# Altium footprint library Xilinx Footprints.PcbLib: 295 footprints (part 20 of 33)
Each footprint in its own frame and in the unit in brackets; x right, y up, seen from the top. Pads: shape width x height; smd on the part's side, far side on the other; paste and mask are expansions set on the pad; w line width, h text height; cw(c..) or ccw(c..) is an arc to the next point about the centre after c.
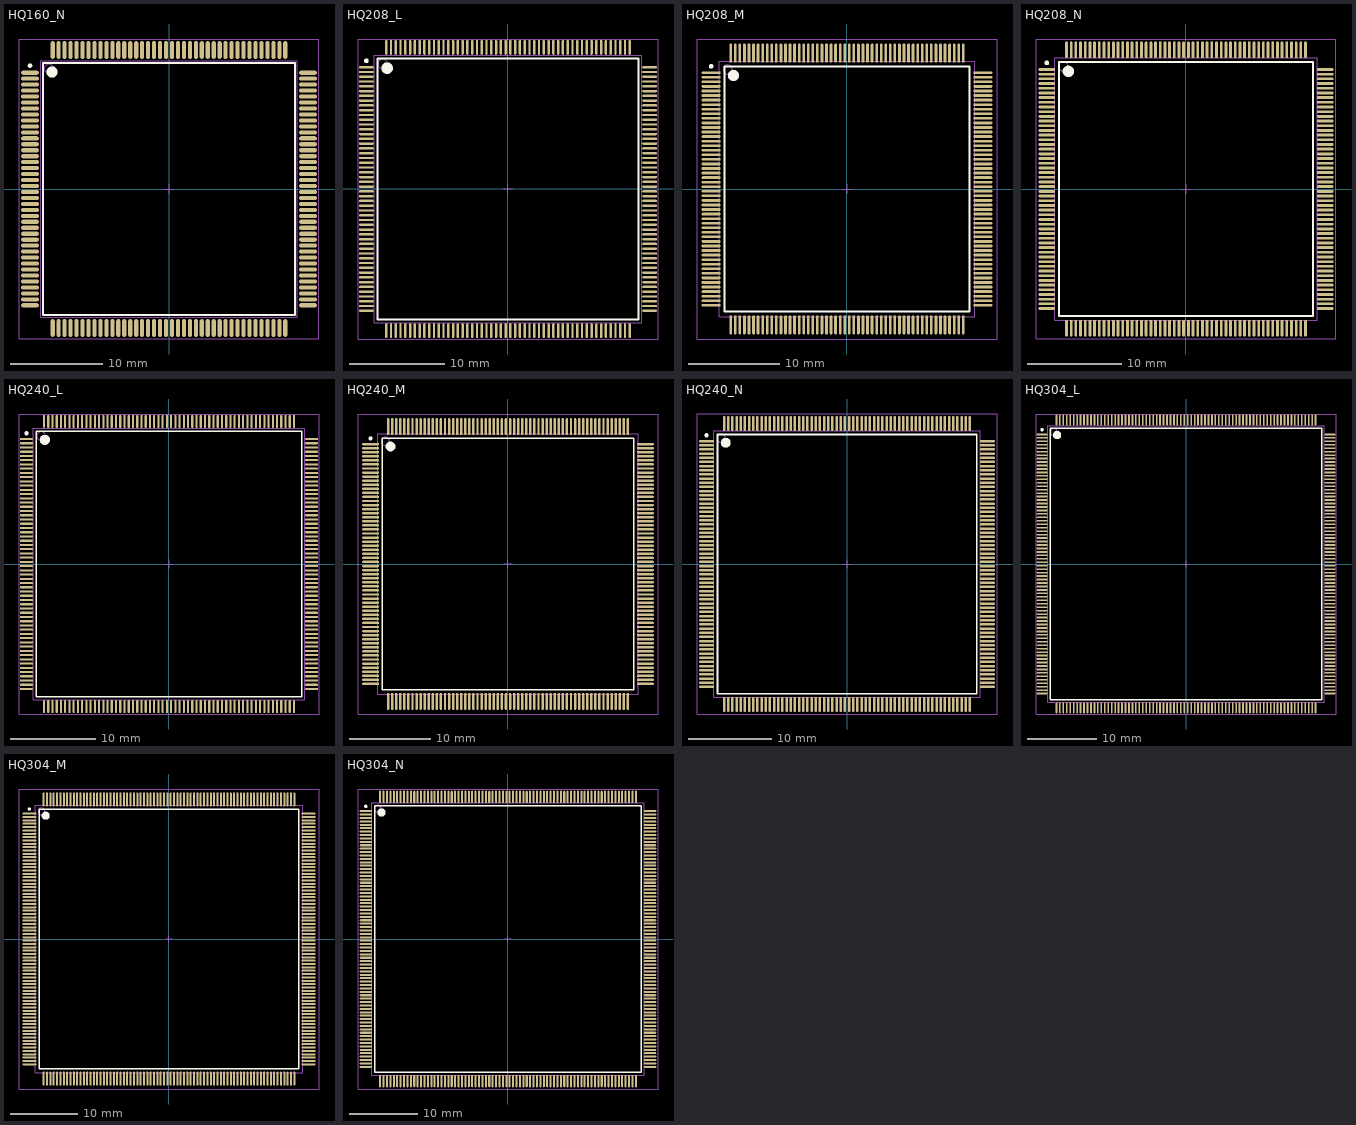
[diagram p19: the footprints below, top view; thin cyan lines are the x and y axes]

## HQ160_N [mm] "160-Pin Heat Sink Quad Flat Pack (HQ160), IPC Medium Density"
height 4.1
pads (160):
  oval 1.95x0.45 smd: 1(-15.15,12.675) 2(-15.15,12.025) 3(-15.15,11.375) 4(-15.15,10.725) 5(-15.15,10.075) 6(-15.15,9.425) 7(-15.15,8.775) 8(-15.15,8.125) 9(-15.15,7.475) 10(-15.15,6.825) 11(-15.15,6.175) 12(-15.15,5.525) 13(-15.15,4.875) 14(-15.15,4.225) 15(-15.15,3.575) 16(-15.15,2.925) 17(-15.15,2.275) 18(-15.15,1.625) 19(-15.15,0.975) 20(-15.15,0.325) 21(-15.15,-0.325) 22(-15.15,-0.975) 23(-15.15,-1.625) 24(-15.15,-2.275) 25(-15.15,-2.925) 26(-15.15,-3.575) 27(-15.15,-4.225) 28(-15.15,-4.875) 29(-15.15,-5.525) 30(-15.15,-6.175) 31(-15.15,-6.825) 32(-15.15,-7.475) 33(-15.15,-8.125) 34(-15.15,-8.775) 35(-15.15,-9.425) 36(-15.15,-10.075) 37(-15.15,-10.725) 38(-15.15,-11.375) 39(-15.15,-12.025) 40(-15.15,-12.675) 81(15.15,-12.675) 82(15.15,-12.025) 83(15.15,-11.375) 84(15.15,-10.725) 85(15.15,-10.075) 86(15.15,-9.425) 87(15.15,-8.775) 88(15.15,-8.125) 89(15.15,-7.475) 90(15.15,-6.825) 91(15.15,-6.175) 92(15.15,-5.525) 93(15.15,-4.875) 94(15.15,-4.225) 95(15.15,-3.575) 96(15.15,-2.925) 97(15.15,-2.275) 98(15.15,-1.625) 99(15.15,-0.975) 100(15.15,-0.325) 101(15.15,0.325) 102(15.15,0.975) 103(15.15,1.625) 104(15.15,2.275) 105(15.15,2.925) 106(15.15,3.575) 107(15.15,4.225) 108(15.15,4.875) 109(15.15,5.525) 110(15.15,6.175) 111(15.15,6.825) 112(15.15,7.475) 113(15.15,8.125) 114(15.15,8.775) 115(15.15,9.425) 116(15.15,10.075) 117(15.15,10.725) 118(15.15,11.375) 119(15.15,12.025) 120(15.15,12.675)
  oval 0.45x1.95 smd: 41(-12.675,-15.15) 42(-12.025,-15.15) 43(-11.375,-15.15) 44(-10.725,-15.15) 45(-10.075,-15.15) 46(-9.425,-15.15) 47(-8.775,-15.15) 48(-8.125,-15.15) 49(-7.475,-15.15) 50(-6.825,-15.15) 51(-6.175,-15.15) 52(-5.525,-15.15) 53(-4.875,-15.15) 54(-4.225,-15.15) 55(-3.575,-15.15) 56(-2.925,-15.15) 57(-2.275,-15.15) 58(-1.625,-15.15) 59(-0.975,-15.15) 60(-0.325,-15.15) 61(0.325,-15.15) 62(0.975,-15.15) 63(1.625,-15.15) 64(2.275,-15.15) 65(2.925,-15.15) 66(3.575,-15.15) 67(4.225,-15.15) 68(4.875,-15.15) 69(5.525,-15.15) 70(6.175,-15.15) 71(6.825,-15.15) 72(7.475,-15.15) 73(8.125,-15.15) 74(8.775,-15.15) 75(9.425,-15.15) 76(10.075,-15.15) 77(10.725,-15.15) 78(11.375,-15.15) 79(12.025,-15.15) 80(12.675,-15.15) 121(12.675,15.15) 122(12.025,15.15) 123(11.375,15.15) 124(10.725,15.15) 125(10.075,15.15) 126(9.425,15.15) 127(8.775,15.15) 128(8.125,15.15) 129(7.475,15.15) 130(6.825,15.15) 131(6.175,15.15) 132(5.525,15.15) 133(4.875,15.15) 134(4.225,15.15) 135(3.575,15.15) 136(2.925,15.15) 137(2.275,15.15) 138(1.625,15.15) 139(0.975,15.15) 140(0.325,15.15) 141(-0.325,15.15) 142(-0.975,15.15) 143(-1.625,15.15) 144(-2.275,15.15) 145(-2.925,15.15) 146(-3.575,15.15) 147(-4.225,15.15) 148(-4.875,15.15) 149(-5.525,15.15) 150(-6.175,15.15) 151(-6.825,15.15) 152(-7.475,15.15) 153(-8.125,15.15) 154(-8.775,15.15) 155(-9.425,15.15) 156(-10.075,15.15) 157(-10.725,15.15) 158(-11.375,15.15) 159(-12.025,15.15) 160(-12.675,15.15)
Top Overlay:
  circle w0.6: c-12.75,12.75 r0.3
  circle w0.25: c-15.15,13.45 r0.125
  lines w0.2: -13.75,-13.75 13.75,-13.75 13.75,13.75 -13.75,13.75 -13.75,-13.75
Mechanical 13:
  circle w0.1: c-13.1,13.1 r0.5
  lines w0.1: -14,-14 14,-14 14,14 -14,14 -14,-14
Mechanical 15:
  lines w0.1: -0.5,0 0.5,0 ; 0,-0.5 0,0.5 ; -16.35,-16.35 16.35,-16.35 16.35,16.35 -16.35,16.35 -16.35,-16.35
3D body: height 4.1, standoff 0, extent -14,-14 14,14

## HQ208_L [mm] "208-Pin Heat Sink Quad Flat Pack (HQ208), IPC High Density"
height 4.1
pads (208):
  oval 1.55x0.25 smd: 1(-14.825,12.75) 2(-14.825,12.25) 3(-14.825,11.75) 4(-14.825,11.25) 5(-14.825,10.75) 6(-14.825,10.25) 7(-14.825,9.75) 8(-14.825,9.25) 9(-14.825,8.75) 10(-14.825,8.25) 11(-14.825,7.75) 12(-14.825,7.25) 13(-14.825,6.75) 14(-14.825,6.25) 15(-14.825,5.75) 16(-14.825,5.25) 17(-14.825,4.75) 18(-14.825,4.25) 19(-14.825,3.75) 20(-14.825,3.25) 21(-14.825,2.75) 22(-14.825,2.25) 23(-14.825,1.75) 24(-14.825,1.25) 25(-14.825,0.75) 26(-14.825,0.25) 27(-14.825,-0.25) 28(-14.825,-0.75) 29(-14.825,-1.25) 30(-14.825,-1.75) 31(-14.825,-2.25) 32(-14.825,-2.75) 33(-14.825,-3.25) 34(-14.825,-3.75) 35(-14.825,-4.25) 36(-14.825,-4.75) 37(-14.825,-5.25) 38(-14.825,-5.75) 39(-14.825,-6.25) 40(-14.825,-6.75) 41(-14.825,-7.25) 42(-14.825,-7.75) 43(-14.825,-8.25) 44(-14.825,-8.75) 45(-14.825,-9.25) 46(-14.825,-9.75) 47(-14.825,-10.25) 48(-14.825,-10.75) 49(-14.825,-11.25) 50(-14.825,-11.75) 51(-14.825,-12.25) 52(-14.825,-12.75) 105(14.825,-12.75) 106(14.825,-12.25) 107(14.825,-11.75) 108(14.825,-11.25) 109(14.825,-10.75) 110(14.825,-10.25) 111(14.825,-9.75) 112(14.825,-9.25) 113(14.825,-8.75) 114(14.825,-8.25) 115(14.825,-7.75) 116(14.825,-7.25) 117(14.825,-6.75) 118(14.825,-6.25) 119(14.825,-5.75) 120(14.825,-5.25) 121(14.825,-4.75) 122(14.825,-4.25) 123(14.825,-3.75) 124(14.825,-3.25) 125(14.825,-2.75) 126(14.825,-2.25) 127(14.825,-1.75) 128(14.825,-1.25) 129(14.825,-0.75) 130(14.825,-0.25) 131(14.825,0.25) 132(14.825,0.75) 133(14.825,1.25) 134(14.825,1.75) 135(14.825,2.25) 136(14.825,2.75) 137(14.825,3.25) 138(14.825,3.75) 139(14.825,4.25) 140(14.825,4.75) 141(14.825,5.25) 142(14.825,5.75) 143(14.825,6.25) 144(14.825,6.75) 145(14.825,7.25) 146(14.825,7.75) 147(14.825,8.25) 148(14.825,8.75) 149(14.825,9.25) 150(14.825,9.75) 151(14.825,10.25) 152(14.825,10.75) 153(14.825,11.25) 154(14.825,11.75) 155(14.825,12.25) 156(14.825,12.75)
  oval 0.25x1.55 smd: 53(-12.75,-14.825) 54(-12.25,-14.825) 55(-11.75,-14.825) 56(-11.25,-14.825) 57(-10.75,-14.825) 58(-10.25,-14.825) 59(-9.75,-14.825) 60(-9.25,-14.825) 61(-8.75,-14.825) 62(-8.25,-14.825) 63(-7.75,-14.825) 64(-7.25,-14.825) 65(-6.75,-14.825) 66(-6.25,-14.825) 67(-5.75,-14.825) 68(-5.25,-14.825) 69(-4.75,-14.825) 70(-4.25,-14.825) 71(-3.75,-14.825) 72(-3.25,-14.825) 73(-2.75,-14.825) 74(-2.25,-14.825) 75(-1.75,-14.825) 76(-1.25,-14.825) 77(-0.75,-14.825) 78(-0.25,-14.825) 79(0.25,-14.825) 80(0.75,-14.825) 81(1.25,-14.825) 82(1.75,-14.825) 83(2.25,-14.825) 84(2.75,-14.825) 85(3.25,-14.825) 86(3.75,-14.825) 87(4.25,-14.825) 88(4.75,-14.825) 89(5.25,-14.825) 90(5.75,-14.825) 91(6.25,-14.825) 92(6.75,-14.825) 93(7.25,-14.825) 94(7.75,-14.825) 95(8.25,-14.825) 96(8.75,-14.825) 97(9.25,-14.825) 98(9.75,-14.825) 99(10.25,-14.825) 100(10.75,-14.825) 101(11.25,-14.825) 102(11.75,-14.825) 103(12.25,-14.825) 104(12.75,-14.825) 157(12.75,14.825) 158(12.25,14.825) 159(11.75,14.825) 160(11.25,14.825) 161(10.75,14.825) 162(10.25,14.825) 163(9.75,14.825) 164(9.25,14.825) 165(8.75,14.825) 166(8.25,14.825) 167(7.75,14.825) 168(7.25,14.825) 169(6.75,14.825) 170(6.25,14.825) 171(5.75,14.825) 172(5.25,14.825) 173(4.75,14.825) 174(4.25,14.825) 175(3.75,14.825) 176(3.25,14.825) 177(2.75,14.825) 178(2.25,14.825) 179(1.75,14.825) 180(1.25,14.825) 181(0.75,14.825) 182(0.25,14.825) 183(-0.25,14.825) 184(-0.75,14.825) 185(-1.25,14.825) 186(-1.75,14.825) 187(-2.25,14.825) 188(-2.75,14.825) 189(-3.25,14.825) 190(-3.75,14.825) 191(-4.25,14.825) 192(-4.75,14.825) 193(-5.25,14.825) 194(-5.75,14.825) 195(-6.25,14.825) 196(-6.75,14.825) 197(-7.25,14.825) 198(-7.75,14.825) 199(-8.25,14.825) 200(-8.75,14.825) 201(-9.25,14.825) 202(-9.75,14.825) 203(-10.25,14.825) 204(-10.75,14.825) 205(-11.25,14.825) 206(-11.75,14.825) 207(-12.25,14.825) 208(-12.75,14.825)
Top Overlay:
  circle w0.6: c-12.65,12.65 r0.3
  circle w0.25: c-14.825,13.425 r0.125
  lines w0.2: -13.65,-13.65 13.65,-13.65 13.65,13.65 -13.65,13.65 -13.65,-13.65
Mechanical 13:
  circle w0.1: c-13.1,13.1 r0.5
  lines w0.1: -14,-14 14,-14 14,14 -14,14 -14,-14
Mechanical 15:
  lines w0.1: -0.5,0 0.5,0 ; 0,-0.5 0,0.5 ; -15.7,-15.7 15.7,-15.7 15.7,15.7 -15.7,15.7 -15.7,-15.7
3D body: height 4.1, standoff 0, extent -14,-14 14,14

## HQ208_M [mm] "208-Pin Heat Sink Quad Flat Pack (HQ208), IPC Low Density"
height 4.1
pads (208):
  oval 2.1x0.3 smd: 1(-14.9,12.75) 2(-14.9,12.25) 3(-14.9,11.75) 4(-14.9,11.25) 5(-14.9,10.75) 6(-14.9,10.25) 7(-14.9,9.75) 8(-14.9,9.25) 9(-14.9,8.75) 10(-14.9,8.25) 11(-14.9,7.75) 12(-14.9,7.25) 13(-14.9,6.75) 14(-14.9,6.25) 15(-14.9,5.75) 16(-14.9,5.25) 17(-14.9,4.75) 18(-14.9,4.25) 19(-14.9,3.75) 20(-14.9,3.25) 21(-14.9,2.75) 22(-14.9,2.25) 23(-14.9,1.75) 24(-14.9,1.25) 25(-14.9,0.75) 26(-14.9,0.25) 27(-14.9,-0.25) 28(-14.9,-0.75) 29(-14.9,-1.25) 30(-14.9,-1.75) 31(-14.9,-2.25) 32(-14.9,-2.75) 33(-14.9,-3.25) 34(-14.9,-3.75) 35(-14.9,-4.25) 36(-14.9,-4.75) 37(-14.9,-5.25) 38(-14.9,-5.75) 39(-14.9,-6.25) 40(-14.9,-6.75) 41(-14.9,-7.25) 42(-14.9,-7.75) 43(-14.9,-8.25) 44(-14.9,-8.75) 45(-14.9,-9.25) 46(-14.9,-9.75) 47(-14.9,-10.25) 48(-14.9,-10.75) 49(-14.9,-11.25) 50(-14.9,-11.75) 51(-14.9,-12.25) 52(-14.9,-12.75) 105(14.9,-12.75) 106(14.9,-12.25) 107(14.9,-11.75) 108(14.9,-11.25) 109(14.9,-10.75) 110(14.9,-10.25) 111(14.9,-9.75) 112(14.9,-9.25) 113(14.9,-8.75) 114(14.9,-8.25) 115(14.9,-7.75) 116(14.9,-7.25) 117(14.9,-6.75) 118(14.9,-6.25) 119(14.9,-5.75) 120(14.9,-5.25) 121(14.9,-4.75) 122(14.9,-4.25) 123(14.9,-3.75) 124(14.9,-3.25) 125(14.9,-2.75) 126(14.9,-2.25) 127(14.9,-1.75) 128(14.9,-1.25) 129(14.9,-0.75) 130(14.9,-0.25) 131(14.9,0.25) 132(14.9,0.75) 133(14.9,1.25) 134(14.9,1.75) 135(14.9,2.25) 136(14.9,2.75) 137(14.9,3.25) 138(14.9,3.75) 139(14.9,4.25) 140(14.9,4.75) 141(14.9,5.25) 142(14.9,5.75) 143(14.9,6.25) 144(14.9,6.75) 145(14.9,7.25) 146(14.9,7.75) 147(14.9,8.25) 148(14.9,8.75) 149(14.9,9.25) 150(14.9,9.75) 151(14.9,10.25) 152(14.9,10.75) 153(14.9,11.25) 154(14.9,11.75) 155(14.9,12.25) 156(14.9,12.75)
  oval 0.3x2.1 smd: 53(-12.75,-14.9) 54(-12.25,-14.9) 55(-11.75,-14.9) 56(-11.25,-14.9) 57(-10.75,-14.9) 58(-10.25,-14.9) 59(-9.75,-14.9) 60(-9.25,-14.9) 61(-8.75,-14.9) 62(-8.25,-14.9) 63(-7.75,-14.9) 64(-7.25,-14.9) 65(-6.75,-14.9) 66(-6.25,-14.9) 67(-5.75,-14.9) 68(-5.25,-14.9) 69(-4.75,-14.9) 70(-4.25,-14.9) 71(-3.75,-14.9) 72(-3.25,-14.9) 73(-2.75,-14.9) 74(-2.25,-14.9) 75(-1.75,-14.9) 76(-1.25,-14.9) 77(-0.75,-14.9) 78(-0.25,-14.9) 79(0.25,-14.9) 80(0.75,-14.9) 81(1.25,-14.9) 82(1.75,-14.9) 83(2.25,-14.9) 84(2.75,-14.9) 85(3.25,-14.9) 86(3.75,-14.9) 87(4.25,-14.9) 88(4.75,-14.9) 89(5.25,-14.9) 90(5.75,-14.9) 91(6.25,-14.9) 92(6.75,-14.9) 93(7.25,-14.9) 94(7.75,-14.9) 95(8.25,-14.9) 96(8.75,-14.9) 97(9.25,-14.9) 98(9.75,-14.9) 99(10.25,-14.9) 100(10.75,-14.9) 101(11.25,-14.9) 102(11.75,-14.9) 103(12.25,-14.9) 104(12.75,-14.9) 157(12.75,14.9) 158(12.25,14.9) 159(11.75,14.9) 160(11.25,14.9) 161(10.75,14.9) 162(10.25,14.9) 163(9.75,14.9) 164(9.25,14.9) 165(8.75,14.9) 166(8.25,14.9) 167(7.75,14.9) 168(7.25,14.9) 169(6.75,14.9) 170(6.25,14.9) 171(5.75,14.9) 172(5.25,14.9) 173(4.75,14.9) 174(4.25,14.9) 175(3.75,14.9) 176(3.25,14.9) 177(2.75,14.9) 178(2.25,14.9) 179(1.75,14.9) 180(1.25,14.9) 181(0.75,14.9) 182(0.25,14.9) 183(-0.25,14.9) 184(-0.75,14.9) 185(-1.25,14.9) 186(-1.75,14.9) 187(-2.25,14.9) 188(-2.75,14.9) 189(-3.25,14.9) 190(-3.75,14.9) 191(-4.25,14.9) 192(-4.75,14.9) 193(-5.25,14.9) 194(-5.75,14.9) 195(-6.25,14.9) 196(-6.75,14.9) 197(-7.25,14.9) 198(-7.75,14.9) 199(-8.25,14.9) 200(-8.75,14.9) 201(-9.25,14.9) 202(-9.75,14.9) 203(-10.25,14.9) 204(-10.75,14.9) 205(-11.25,14.9) 206(-11.75,14.9) 207(-12.25,14.9) 208(-12.75,14.9)
Top Overlay:
  circle w0.6: c-12.45,12.45 r0.3
  circle w0.25: c-14.9,13.45 r0.125
  lines w0.2: -13.45,-13.45 13.45,-13.45 13.45,13.45 -13.45,13.45 -13.45,-13.45
Mechanical 13:
  circle w0.1: c-13.1,13.1 r0.5
  lines w0.1: -14,-14 14,-14 14,14 -14,14 -14,-14
Mechanical 15:
  lines w0.1: -0.5,0 0.5,0 ; 0,-0.5 0,0.5 ; -16.45,-16.45 16.45,-16.45 16.45,16.45 -16.45,16.45 -16.45,-16.45
3D body: height 4.1, standoff 0, extent -14,-14 14,14

## HQ208_N [mm] "208-Pin Heat Sink Quad Flat Pack (HQ208), IPC Medium Density"
height 4.1
pads (208):
  oval 1.8x0.3 smd: 1(-14.85,12.75) 2(-14.85,12.25) 3(-14.85,11.75) 4(-14.85,11.25) 5(-14.85,10.75) 6(-14.85,10.25) 7(-14.85,9.75) 8(-14.85,9.25) 9(-14.85,8.75) 10(-14.85,8.25) 11(-14.85,7.75) 12(-14.85,7.25) 13(-14.85,6.75) 14(-14.85,6.25) 15(-14.85,5.75) 16(-14.85,5.25) 17(-14.85,4.75) 18(-14.85,4.25) 19(-14.85,3.75) 20(-14.85,3.25) 21(-14.85,2.75) 22(-14.85,2.25) 23(-14.85,1.75) 24(-14.85,1.25) 25(-14.85,0.75) 26(-14.85,0.25) 27(-14.85,-0.25) 28(-14.85,-0.75) 29(-14.85,-1.25) 30(-14.85,-1.75) 31(-14.85,-2.25) 32(-14.85,-2.75) 33(-14.85,-3.25) 34(-14.85,-3.75) 35(-14.85,-4.25) 36(-14.85,-4.75) 37(-14.85,-5.25) 38(-14.85,-5.75) 39(-14.85,-6.25) 40(-14.85,-6.75) 41(-14.85,-7.25) 42(-14.85,-7.75) 43(-14.85,-8.25) 44(-14.85,-8.75) 45(-14.85,-9.25) 46(-14.85,-9.75) 47(-14.85,-10.25) 48(-14.85,-10.75) 49(-14.85,-11.25) 50(-14.85,-11.75) 51(-14.85,-12.25) 52(-14.85,-12.75) 105(14.85,-12.75) 106(14.85,-12.25) 107(14.85,-11.75) 108(14.85,-11.25) 109(14.85,-10.75) 110(14.85,-10.25) 111(14.85,-9.75) 112(14.85,-9.25) 113(14.85,-8.75) 114(14.85,-8.25) 115(14.85,-7.75) 116(14.85,-7.25) 117(14.85,-6.75) 118(14.85,-6.25) 119(14.85,-5.75) 120(14.85,-5.25) 121(14.85,-4.75) 122(14.85,-4.25) 123(14.85,-3.75) 124(14.85,-3.25) 125(14.85,-2.75) 126(14.85,-2.25) 127(14.85,-1.75) 128(14.85,-1.25) 129(14.85,-0.75) 130(14.85,-0.25) 131(14.85,0.25) 132(14.85,0.75) 133(14.85,1.25) 134(14.85,1.75) 135(14.85,2.25) 136(14.85,2.75) 137(14.85,3.25) 138(14.85,3.75) 139(14.85,4.25) 140(14.85,4.75) 141(14.85,5.25) 142(14.85,5.75) 143(14.85,6.25) 144(14.85,6.75) 145(14.85,7.25) 146(14.85,7.75) 147(14.85,8.25) 148(14.85,8.75) 149(14.85,9.25) 150(14.85,9.75) 151(14.85,10.25) 152(14.85,10.75) 153(14.85,11.25) 154(14.85,11.75) 155(14.85,12.25) 156(14.85,12.75)
  oval 0.3x1.8 smd: 53(-12.75,-14.85) 54(-12.25,-14.85) 55(-11.75,-14.85) 56(-11.25,-14.85) 57(-10.75,-14.85) 58(-10.25,-14.85) 59(-9.75,-14.85) 60(-9.25,-14.85) 61(-8.75,-14.85) 62(-8.25,-14.85) 63(-7.75,-14.85) 64(-7.25,-14.85) 65(-6.75,-14.85) 66(-6.25,-14.85) 67(-5.75,-14.85) 68(-5.25,-14.85) 69(-4.75,-14.85) 70(-4.25,-14.85) 71(-3.75,-14.85) 72(-3.25,-14.85) 73(-2.75,-14.85) 74(-2.25,-14.85) 75(-1.75,-14.85) 76(-1.25,-14.85) 77(-0.75,-14.85) 78(-0.25,-14.85) 79(0.25,-14.85) 80(0.75,-14.85) 81(1.25,-14.85) 82(1.75,-14.85) 83(2.25,-14.85) 84(2.75,-14.85) 85(3.25,-14.85) 86(3.75,-14.85) 87(4.25,-14.85) 88(4.75,-14.85) 89(5.25,-14.85) 90(5.75,-14.85) 91(6.25,-14.85) 92(6.75,-14.85) 93(7.25,-14.85) 94(7.75,-14.85) 95(8.25,-14.85) 96(8.75,-14.85) 97(9.25,-14.85) 98(9.75,-14.85) 99(10.25,-14.85) 100(10.75,-14.85) 101(11.25,-14.85) 102(11.75,-14.85) 103(12.25,-14.85) 104(12.75,-14.85) 157(12.75,14.85) 158(12.25,14.85) 159(11.75,14.85) 160(11.25,14.85) 161(10.75,14.85) 162(10.25,14.85) 163(9.75,14.85) 164(9.25,14.85) 165(8.75,14.85) 166(8.25,14.85) 167(7.75,14.85) 168(7.25,14.85) 169(6.75,14.85) 170(6.25,14.85) 171(5.75,14.85) 172(5.25,14.85) 173(4.75,14.85) 174(4.25,14.85) 175(3.75,14.85) 176(3.25,14.85) 177(2.75,14.85) 178(2.25,14.85) 179(1.75,14.85) 180(1.25,14.85) 181(0.75,14.85) 182(0.25,14.85) 183(-0.25,14.85) 184(-0.75,14.85) 185(-1.25,14.85) 186(-1.75,14.85) 187(-2.25,14.85) 188(-2.75,14.85) 189(-3.25,14.85) 190(-3.75,14.85) 191(-4.25,14.85) 192(-4.75,14.85) 193(-5.25,14.85) 194(-5.75,14.85) 195(-6.25,14.85) 196(-6.75,14.85) 197(-7.25,14.85) 198(-7.75,14.85) 199(-8.25,14.85) 200(-8.75,14.85) 201(-9.25,14.85) 202(-9.75,14.85) 203(-10.25,14.85) 204(-10.75,14.85) 205(-11.25,14.85) 206(-11.75,14.85) 207(-12.25,14.85) 208(-12.75,14.85)
Top Overlay:
  circle w0.6: c-12.55,12.55 r0.3
  circle w0.25: c-14.85,13.45 r0.125
  lines w0.2: -13.55,-13.55 13.55,-13.55 13.55,13.55 -13.55,13.55 -13.55,-13.55
Mechanical 13:
  circle w0.1: c-13.1,13.1 r0.5
  lines w0.1: -14,-14 14,-14 14,14 -14,14 -14,-14
Mechanical 15:
  lines w0.1: -0.5,0 0.5,0 ; 0,-0.5 0,0.5 ; -16,-16 16,-16 16,16 -16,16 -16,-16
3D body: height 4.1, standoff 0, extent -14,-14 14,14

## HQ240_L [mm] "240-Pin Heat Sink Quad Flat Pack (HQ240), IPC High Density"
height 4.1
pads (240):
  oval 1.55x0.25 smd: 1(-16.825,14.75) 2(-16.825,14.25) 3(-16.825,13.75) 4(-16.825,13.25) 5(-16.825,12.75) 6(-16.825,12.25) 7(-16.825,11.75) 8(-16.825,11.25) 9(-16.825,10.75) 10(-16.825,10.25) 11(-16.825,9.75) 12(-16.825,9.25) 13(-16.825,8.75) 14(-16.825,8.25) 15(-16.825,7.75) 16(-16.825,7.25) 17(-16.825,6.75) 18(-16.825,6.25) 19(-16.825,5.75) 20(-16.825,5.25) 21(-16.825,4.75) 22(-16.825,4.25) 23(-16.825,3.75) 24(-16.825,3.25) 25(-16.825,2.75) 26(-16.825,2.25) 27(-16.825,1.75) 28(-16.825,1.25) 29(-16.825,0.75) 30(-16.825,0.25) 31(-16.825,-0.25) 32(-16.825,-0.75) 33(-16.825,-1.25) 34(-16.825,-1.75) 35(-16.825,-2.25) 36(-16.825,-2.75) 37(-16.825,-3.25) 38(-16.825,-3.75) 39(-16.825,-4.25) 40(-16.825,-4.75) 41(-16.825,-5.25) 42(-16.825,-5.75) 43(-16.825,-6.25) 44(-16.825,-6.75) 45(-16.825,-7.25) 46(-16.825,-7.75) 47(-16.825,-8.25) 48(-16.825,-8.75) 49(-16.825,-9.25) 50(-16.825,-9.75) 51(-16.825,-10.25) 52(-16.825,-10.75) 53(-16.825,-11.25) 54(-16.825,-11.75) 55(-16.825,-12.25) 56(-16.825,-12.75) 57(-16.825,-13.25) 58(-16.825,-13.75) 59(-16.825,-14.25) 60(-16.825,-14.75) 121(16.825,-14.75) 122(16.825,-14.25) 123(16.825,-13.75) 124(16.825,-13.25) 125(16.825,-12.75) 126(16.825,-12.25) 127(16.825,-11.75) 128(16.825,-11.25) 129(16.825,-10.75) 130(16.825,-10.25) 131(16.825,-9.75) 132(16.825,-9.25) 133(16.825,-8.75) 134(16.825,-8.25) 135(16.825,-7.75) 136(16.825,-7.25) 137(16.825,-6.75) 138(16.825,-6.25) 139(16.825,-5.75) 140(16.825,-5.25) 141(16.825,-4.75) 142(16.825,-4.25) 143(16.825,-3.75) 144(16.825,-3.25) 145(16.825,-2.75) 146(16.825,-2.25) 147(16.825,-1.75) 148(16.825,-1.25) 149(16.825,-0.75) 150(16.825,-0.25) 151(16.825,0.25) 152(16.825,0.75) 153(16.825,1.25) 154(16.825,1.75) 155(16.825,2.25) 156(16.825,2.75) 157(16.825,3.25) 158(16.825,3.75) 159(16.825,4.25) 160(16.825,4.75) 161(16.825,5.25) 162(16.825,5.75) 163(16.825,6.25) 164(16.825,6.75) 165(16.825,7.25) 166(16.825,7.75) 167(16.825,8.25) 168(16.825,8.75) 169(16.825,9.25) 170(16.825,9.75) 171(16.825,10.25) 172(16.825,10.75) 173(16.825,11.25) 174(16.825,11.75) 175(16.825,12.25) 176(16.825,12.75) 177(16.825,13.25) 178(16.825,13.75) 179(16.825,14.25) 180(16.825,14.75)
  oval 0.25x1.55 smd: 61(-14.75,-16.825) 62(-14.25,-16.825) 63(-13.75,-16.825) 64(-13.25,-16.825) 65(-12.75,-16.825) 66(-12.25,-16.825) 67(-11.75,-16.825) 68(-11.25,-16.825) 69(-10.75,-16.825) 70(-10.25,-16.825) 71(-9.75,-16.825) 72(-9.25,-16.825) 73(-8.75,-16.825) 74(-8.25,-16.825) 75(-7.75,-16.825) 76(-7.25,-16.825) 77(-6.75,-16.825) 78(-6.25,-16.825) 79(-5.75,-16.825) 80(-5.25,-16.825) 81(-4.75,-16.825) 82(-4.25,-16.825) 83(-3.75,-16.825) 84(-3.25,-16.825) 85(-2.75,-16.825) 86(-2.25,-16.825) 87(-1.75,-16.825) 88(-1.25,-16.825) 89(-0.75,-16.825) 90(-0.25,-16.825) 91(0.25,-16.825) 92(0.75,-16.825) 93(1.25,-16.825) 94(1.75,-16.825) 95(2.25,-16.825) 96(2.75,-16.825) 97(3.25,-16.825) 98(3.75,-16.825) 99(4.25,-16.825) 100(4.75,-16.825) 101(5.25,-16.825) 102(5.75,-16.825) 103(6.25,-16.825) 104(6.75,-16.825) 105(7.25,-16.825) 106(7.75,-16.825) 107(8.25,-16.825) 108(8.75,-16.825) 109(9.25,-16.825) 110(9.75,-16.825) 111(10.25,-16.825) 112(10.75,-16.825) 113(11.25,-16.825) 114(11.75,-16.825) 115(12.25,-16.825) 116(12.75,-16.825) 117(13.25,-16.825) 118(13.75,-16.825) 119(14.25,-16.825) 120(14.75,-16.825) 181(14.75,16.825) 182(14.25,16.825) 183(13.75,16.825) 184(13.25,16.825) 185(12.75,16.825) 186(12.25,16.825) 187(11.75,16.825) 188(11.25,16.825) 189(10.75,16.825) 190(10.25,16.825) 191(9.75,16.825) 192(9.25,16.825) 193(8.75,16.825) 194(8.25,16.825) 195(7.75,16.825) 196(7.25,16.825) 197(6.75,16.825) 198(6.25,16.825) 199(5.75,16.825) 200(5.25,16.825) 201(4.75,16.825) 202(4.25,16.825) 203(3.75,16.825) 204(3.25,16.825) 205(2.75,16.825) 206(2.25,16.825) 207(1.75,16.825) 208(1.25,16.825) 209(0.75,16.825) 210(0.25,16.825) 211(-0.25,16.825) 212(-0.75,16.825) 213(-1.25,16.825) 214(-1.75,16.825) 215(-2.25,16.825) 216(-2.75,16.825) 217(-3.25,16.825) 218(-3.75,16.825) 219(-4.25,16.825) 220(-4.75,16.825) 221(-5.25,16.825) 222(-5.75,16.825) 223(-6.25,16.825) 224(-6.75,16.825) 225(-7.25,16.825) 226(-7.75,16.825) 227(-8.25,16.825) 228(-8.75,16.825) 229(-9.25,16.825) 230(-9.75,16.825) 231(-10.25,16.825) 232(-10.75,16.825) 233(-11.25,16.825) 234(-11.75,16.825) 235(-12.25,16.825) 236(-12.75,16.825) 237(-13.25,16.825) 238(-13.75,16.825) 239(-14.25,16.825) 240(-14.75,16.825)
Top Overlay:
  circle w0.6: c-14.65,14.65 r0.3
  circle w0.25: c-16.825,15.425 r0.125
  lines w0.2: -15.65,-15.65 15.65,-15.65 15.65,15.65 -15.65,15.65 -15.65,-15.65
Mechanical 13:
  circle w0.1: c-15.1,15.1 r0.5
  lines w0.1: -16,-16 16,-16 16,16 -16,16 -16,-16
Mechanical 15:
  lines w0.1: -0.5,0 0.5,0 ; 0,-0.5 0,0.5 ; -17.7,-17.7 17.7,-17.7 17.7,17.7 -17.7,17.7 -17.7,-17.7
3D body: height 4.1, standoff 0, extent -16,-16 16,16

## HQ240_M [mm] "240-Pin Heat Sink Quad Flat Pack (HQ240), IPC Low Density"
height 4.1
pads (240):
  oval 2.1x0.3 smd: 1(-16.9,14.75) 2(-16.9,14.25) 3(-16.9,13.75) 4(-16.9,13.25) 5(-16.9,12.75) 6(-16.9,12.25) 7(-16.9,11.75) 8(-16.9,11.25) 9(-16.9,10.75) 10(-16.9,10.25) 11(-16.9,9.75) 12(-16.9,9.25) 13(-16.9,8.75) 14(-16.9,8.25) 15(-16.9,7.75) 16(-16.9,7.25) 17(-16.9,6.75) 18(-16.9,6.25) 19(-16.9,5.75) 20(-16.9,5.25) 21(-16.9,4.75) 22(-16.9,4.25) 23(-16.9,3.75) 24(-16.9,3.25) 25(-16.9,2.75) 26(-16.9,2.25) 27(-16.9,1.75) 28(-16.9,1.25) 29(-16.9,0.75) 30(-16.9,0.25) 31(-16.9,-0.25) 32(-16.9,-0.75) 33(-16.9,-1.25) 34(-16.9,-1.75) 35(-16.9,-2.25) 36(-16.9,-2.75) 37(-16.9,-3.25) 38(-16.9,-3.75) 39(-16.9,-4.25) 40(-16.9,-4.75) 41(-16.9,-5.25) 42(-16.9,-5.75) 43(-16.9,-6.25) 44(-16.9,-6.75) 45(-16.9,-7.25) 46(-16.9,-7.75) 47(-16.9,-8.25) 48(-16.9,-8.75) 49(-16.9,-9.25) 50(-16.9,-9.75) 51(-16.9,-10.25) 52(-16.9,-10.75) 53(-16.9,-11.25) 54(-16.9,-11.75) 55(-16.9,-12.25) 56(-16.9,-12.75) 57(-16.9,-13.25) 58(-16.9,-13.75) 59(-16.9,-14.25) 60(-16.9,-14.75) 121(16.9,-14.75) 122(16.9,-14.25) 123(16.9,-13.75) 124(16.9,-13.25) 125(16.9,-12.75) 126(16.9,-12.25) 127(16.9,-11.75) 128(16.9,-11.25) 129(16.9,-10.75) 130(16.9,-10.25) 131(16.9,-9.75) 132(16.9,-9.25) 133(16.9,-8.75) 134(16.9,-8.25) 135(16.9,-7.75) 136(16.9,-7.25) 137(16.9,-6.75) 138(16.9,-6.25) 139(16.9,-5.75) 140(16.9,-5.25) 141(16.9,-4.75) 142(16.9,-4.25) 143(16.9,-3.75) 144(16.9,-3.25) 145(16.9,-2.75) 146(16.9,-2.25) 147(16.9,-1.75) 148(16.9,-1.25) 149(16.9,-0.75) 150(16.9,-0.25) 151(16.9,0.25) 152(16.9,0.75) 153(16.9,1.25) 154(16.9,1.75) 155(16.9,2.25) 156(16.9,2.75) 157(16.9,3.25) 158(16.9,3.75) 159(16.9,4.25) 160(16.9,4.75) 161(16.9,5.25) 162(16.9,5.75) 163(16.9,6.25) 164(16.9,6.75) 165(16.9,7.25) 166(16.9,7.75) 167(16.9,8.25) 168(16.9,8.75) 169(16.9,9.25) 170(16.9,9.75) 171(16.9,10.25) 172(16.9,10.75) 173(16.9,11.25) 174(16.9,11.75) 175(16.9,12.25) 176(16.9,12.75) 177(16.9,13.25) 178(16.9,13.75) 179(16.9,14.25) 180(16.9,14.75)
  oval 0.3x2.1 smd: 61(-14.75,-16.9) 62(-14.25,-16.9) 63(-13.75,-16.9) 64(-13.25,-16.9) 65(-12.75,-16.9) 66(-12.25,-16.9) 67(-11.75,-16.9) 68(-11.25,-16.9) 69(-10.75,-16.9) 70(-10.25,-16.9) 71(-9.75,-16.9) 72(-9.25,-16.9) 73(-8.75,-16.9) 74(-8.25,-16.9) 75(-7.75,-16.9) 76(-7.25,-16.9) 77(-6.75,-16.9) 78(-6.25,-16.9) 79(-5.75,-16.9) 80(-5.25,-16.9) 81(-4.75,-16.9) 82(-4.25,-16.9) 83(-3.75,-16.9) 84(-3.25,-16.9) 85(-2.75,-16.9) 86(-2.25,-16.9) 87(-1.75,-16.9) 88(-1.25,-16.9) 89(-0.75,-16.9) 90(-0.25,-16.9) 91(0.25,-16.9) 92(0.75,-16.9) 93(1.25,-16.9) 94(1.75,-16.9) 95(2.25,-16.9) 96(2.75,-16.9) 97(3.25,-16.9) 98(3.75,-16.9) 99(4.25,-16.9) 100(4.75,-16.9) 101(5.25,-16.9) 102(5.75,-16.9) 103(6.25,-16.9) 104(6.75,-16.9) 105(7.25,-16.9) 106(7.75,-16.9) 107(8.25,-16.9) 108(8.75,-16.9) 109(9.25,-16.9) 110(9.75,-16.9) 111(10.25,-16.9) 112(10.75,-16.9) 113(11.25,-16.9) 114(11.75,-16.9) 115(12.25,-16.9) 116(12.75,-16.9) 117(13.25,-16.9) 118(13.75,-16.9) 119(14.25,-16.9) 120(14.75,-16.9) 181(14.75,16.9) 182(14.25,16.9) 183(13.75,16.9) 184(13.25,16.9) 185(12.75,16.9) 186(12.25,16.9) 187(11.75,16.9) 188(11.25,16.9) 189(10.75,16.9) 190(10.25,16.9) 191(9.75,16.9) 192(9.25,16.9) 193(8.75,16.9) 194(8.25,16.9) 195(7.75,16.9) 196(7.25,16.9) 197(6.75,16.9) 198(6.25,16.9) 199(5.75,16.9) 200(5.25,16.9) 201(4.75,16.9) 202(4.25,16.9) 203(3.75,16.9) 204(3.25,16.9) 205(2.75,16.9) 206(2.25,16.9) 207(1.75,16.9) 208(1.25,16.9) 209(0.75,16.9) 210(0.25,16.9) 211(-0.25,16.9) 212(-0.75,16.9) 213(-1.25,16.9) 214(-1.75,16.9) 215(-2.25,16.9) 216(-2.75,16.9) 217(-3.25,16.9) 218(-3.75,16.9) 219(-4.25,16.9) 220(-4.75,16.9) 221(-5.25,16.9) 222(-5.75,16.9) 223(-6.25,16.9) 224(-6.75,16.9) 225(-7.25,16.9) 226(-7.75,16.9) 227(-8.25,16.9) 228(-8.75,16.9) 229(-9.25,16.9) 230(-9.75,16.9) 231(-10.25,16.9) 232(-10.75,16.9) 233(-11.25,16.9) 234(-11.75,16.9) 235(-12.25,16.9) 236(-12.75,16.9) 237(-13.25,16.9) 238(-13.75,16.9) 239(-14.25,16.9) 240(-14.75,16.9)
Top Overlay:
  circle w0.6: c-14.45,14.45 r0.3
  circle w0.25: c-16.9,15.45 r0.125
  lines w0.2: -15.45,-15.45 15.45,-15.45 15.45,15.45 -15.45,15.45 -15.45,-15.45
Mechanical 13:
  circle w0.1: c-15.1,15.1 r0.5
  lines w0.1: -16,-16 16,-16 16,16 -16,16 -16,-16
Mechanical 15:
  lines w0.1: -0.5,0 0.5,0 ; 0,-0.5 0,0.5 ; -18.45,-18.45 18.45,-18.45 18.45,18.45 -18.45,18.45 -18.45,-18.45
3D body: height 4.1, standoff 0, extent -16,-16 16,16

## HQ240_N [mm] "240-Pin Heat Sink Quad Flat Pack (HQ240), IPC Medium Density"
height 4.1
pads (240):
  oval 1.8x0.3 smd: 1(-16.85,14.75) 2(-16.85,14.25) 3(-16.85,13.75) 4(-16.85,13.25) 5(-16.85,12.75) 6(-16.85,12.25) 7(-16.85,11.75) 8(-16.85,11.25) 9(-16.85,10.75) 10(-16.85,10.25) 11(-16.85,9.75) 12(-16.85,9.25) 13(-16.85,8.75) 14(-16.85,8.25) 15(-16.85,7.75) 16(-16.85,7.25) 17(-16.85,6.75) 18(-16.85,6.25) 19(-16.85,5.75) 20(-16.85,5.25) 21(-16.85,4.75) 22(-16.85,4.25) 23(-16.85,3.75) 24(-16.85,3.25) 25(-16.85,2.75) 26(-16.85,2.25) 27(-16.85,1.75) 28(-16.85,1.25) 29(-16.85,0.75) 30(-16.85,0.25) 31(-16.85,-0.25) 32(-16.85,-0.75) 33(-16.85,-1.25) 34(-16.85,-1.75) 35(-16.85,-2.25) 36(-16.85,-2.75) 37(-16.85,-3.25) 38(-16.85,-3.75) 39(-16.85,-4.25) 40(-16.85,-4.75) 41(-16.85,-5.25) 42(-16.85,-5.75) 43(-16.85,-6.25) 44(-16.85,-6.75) 45(-16.85,-7.25) 46(-16.85,-7.75) 47(-16.85,-8.25) 48(-16.85,-8.75) 49(-16.85,-9.25) 50(-16.85,-9.75) 51(-16.85,-10.25) 52(-16.85,-10.75) 53(-16.85,-11.25) 54(-16.85,-11.75) 55(-16.85,-12.25) 56(-16.85,-12.75) 57(-16.85,-13.25) 58(-16.85,-13.75) 59(-16.85,-14.25) 60(-16.85,-14.75) 121(16.85,-14.75) 122(16.85,-14.25) 123(16.85,-13.75) 124(16.85,-13.25) 125(16.85,-12.75) 126(16.85,-12.25) 127(16.85,-11.75) 128(16.85,-11.25) 129(16.85,-10.75) 130(16.85,-10.25) 131(16.85,-9.75) 132(16.85,-9.25) 133(16.85,-8.75) 134(16.85,-8.25) 135(16.85,-7.75) 136(16.85,-7.25) 137(16.85,-6.75) 138(16.85,-6.25) 139(16.85,-5.75) 140(16.85,-5.25) 141(16.85,-4.75) 142(16.85,-4.25) 143(16.85,-3.75) 144(16.85,-3.25) 145(16.85,-2.75) 146(16.85,-2.25) 147(16.85,-1.75) 148(16.85,-1.25) 149(16.85,-0.75) 150(16.85,-0.25) 151(16.85,0.25) 152(16.85,0.75) 153(16.85,1.25) 154(16.85,1.75) 155(16.85,2.25) 156(16.85,2.75) 157(16.85,3.25) 158(16.85,3.75) 159(16.85,4.25) 160(16.85,4.75) 161(16.85,5.25) 162(16.85,5.75) 163(16.85,6.25) 164(16.85,6.75) 165(16.85,7.25) 166(16.85,7.75) 167(16.85,8.25) 168(16.85,8.75) 169(16.85,9.25) 170(16.85,9.75) 171(16.85,10.25) 172(16.85,10.75) 173(16.85,11.25) 174(16.85,11.75) 175(16.85,12.25) 176(16.85,12.75) 177(16.85,13.25) 178(16.85,13.75) 179(16.85,14.25) 180(16.85,14.75)
  oval 0.3x1.8 smd: 61(-14.75,-16.85) 62(-14.25,-16.85) 63(-13.75,-16.85) 64(-13.25,-16.85) 65(-12.75,-16.85) 66(-12.25,-16.85) 67(-11.75,-16.85) 68(-11.25,-16.85) 69(-10.75,-16.85) 70(-10.25,-16.85) 71(-9.75,-16.85) 72(-9.25,-16.85) 73(-8.75,-16.85) 74(-8.25,-16.85) 75(-7.75,-16.85) 76(-7.25,-16.85) 77(-6.75,-16.85) 78(-6.25,-16.85) 79(-5.75,-16.85) 80(-5.25,-16.85) 81(-4.75,-16.85) 82(-4.25,-16.85) 83(-3.75,-16.85) 84(-3.25,-16.85) 85(-2.75,-16.85) 86(-2.25,-16.85) 87(-1.75,-16.85) 88(-1.25,-16.85) 89(-0.75,-16.85) 90(-0.25,-16.85) 91(0.25,-16.85) 92(0.75,-16.85) 93(1.25,-16.85) 94(1.75,-16.85) 95(2.25,-16.85) 96(2.75,-16.85) 97(3.25,-16.85) 98(3.75,-16.85) 99(4.25,-16.85) 100(4.75,-16.85) 101(5.25,-16.85) 102(5.75,-16.85) 103(6.25,-16.85) 104(6.75,-16.85) 105(7.25,-16.85) 106(7.75,-16.85) 107(8.25,-16.85) 108(8.75,-16.85) 109(9.25,-16.85) 110(9.75,-16.85) 111(10.25,-16.85) 112(10.75,-16.85) 113(11.25,-16.85) 114(11.75,-16.85) 115(12.25,-16.85) 116(12.75,-16.85) 117(13.25,-16.85) 118(13.75,-16.85) 119(14.25,-16.85) 120(14.75,-16.85) 181(14.75,16.85) 182(14.25,16.85) 183(13.75,16.85) 184(13.25,16.85) 185(12.75,16.85) 186(12.25,16.85) 187(11.75,16.85) 188(11.25,16.85) 189(10.75,16.85) 190(10.25,16.85) 191(9.75,16.85) 192(9.25,16.85) 193(8.75,16.85) 194(8.25,16.85) 195(7.75,16.85) 196(7.25,16.85) 197(6.75,16.85) 198(6.25,16.85) 199(5.75,16.85) 200(5.25,16.85) 201(4.75,16.85) 202(4.25,16.85) 203(3.75,16.85) 204(3.25,16.85) 205(2.75,16.85) 206(2.25,16.85) 207(1.75,16.85) 208(1.25,16.85) 209(0.75,16.85) 210(0.25,16.85) 211(-0.25,16.85) 212(-0.75,16.85) 213(-1.25,16.85) 214(-1.75,16.85) 215(-2.25,16.85) 216(-2.75,16.85) 217(-3.25,16.85) 218(-3.75,16.85) 219(-4.25,16.85) 220(-4.75,16.85) 221(-5.25,16.85) 222(-5.75,16.85) 223(-6.25,16.85) 224(-6.75,16.85) 225(-7.25,16.85) 226(-7.75,16.85) 227(-8.25,16.85) 228(-8.75,16.85) 229(-9.25,16.85) 230(-9.75,16.85) 231(-10.25,16.85) 232(-10.75,16.85) 233(-11.25,16.85) 234(-11.75,16.85) 235(-12.25,16.85) 236(-12.75,16.85) 237(-13.25,16.85) 238(-13.75,16.85) 239(-14.25,16.85) 240(-14.75,16.85)
Top Overlay:
  circle w0.6: c-14.55,14.55 r0.3
  circle w0.25: c-16.85,15.45 r0.125
  lines w0.2: -15.55,-15.55 15.55,-15.55 15.55,15.55 -15.55,15.55 -15.55,-15.55
Mechanical 13:
  circle w0.1: c-15.1,15.1 r0.5
  lines w0.1: -16,-16 16,-16 16,16 -16,16 -16,-16
Mechanical 15:
  lines w0.1: -0.5,0 0.5,0 ; 0,-0.5 0,0.5 ; -18,-18 18,-18 18,18 -18,18 -18,-18
3D body: height 4.1, standoff 0, extent -16,-16 16,16

## HQ304_L [mm] "304-Pin Heat Sink Quad Flat Pack (HQ304), IPC High Density"
height 4.5
pads (304):
  oval 1.55x0.25 smd: 1(-20.825,18.75) 2(-20.825,18.25) 3(-20.825,17.75) 4(-20.825,17.25) 5(-20.825,16.75) 6(-20.825,16.25) 7(-20.825,15.75) 8(-20.825,15.25) 9(-20.825,14.75) 10(-20.825,14.25) 11(-20.825,13.75) 12(-20.825,13.25) 13(-20.825,12.75) 14(-20.825,12.25) 15(-20.825,11.75) 16(-20.825,11.25) 17(-20.825,10.75) 18(-20.825,10.25) 19(-20.825,9.75) 20(-20.825,9.25) 21(-20.825,8.75) 22(-20.825,8.25) 23(-20.825,7.75) 24(-20.825,7.25) 25(-20.825,6.75) 26(-20.825,6.25) 27(-20.825,5.75) 28(-20.825,5.25) 29(-20.825,4.75) 30(-20.825,4.25) 31(-20.825,3.75) 32(-20.825,3.25) 33(-20.825,2.75) 34(-20.825,2.25) 35(-20.825,1.75) 36(-20.825,1.25) 37(-20.825,0.75) 38(-20.825,0.25) 39(-20.825,-0.25) 40(-20.825,-0.75) 41(-20.825,-1.25) 42(-20.825,-1.75) 43(-20.825,-2.25) 44(-20.825,-2.75) 45(-20.825,-3.25) 46(-20.825,-3.75) 47(-20.825,-4.25) 48(-20.825,-4.75) 49(-20.825,-5.25) 50(-20.825,-5.75) 51(-20.825,-6.25) 52(-20.825,-6.75) 53(-20.825,-7.25) 54(-20.825,-7.75) 55(-20.825,-8.25) 56(-20.825,-8.75) 57(-20.825,-9.25) 58(-20.825,-9.75) 59(-20.825,-10.25) 60(-20.825,-10.75) 61(-20.825,-11.25) 62(-20.825,-11.75) 63(-20.825,-12.25) 64(-20.825,-12.75) 65(-20.825,-13.25) 66(-20.825,-13.75) 67(-20.825,-14.25) 68(-20.825,-14.75) 69(-20.825,-15.25) 70(-20.825,-15.75) 71(-20.825,-16.25) 72(-20.825,-16.75) 73(-20.825,-17.25) 74(-20.825,-17.75) 75(-20.825,-18.25) 76(-20.825,-18.75) 153(20.825,-18.75) 154(20.825,-18.25) 155(20.825,-17.75) 156(20.825,-17.25) 157(20.825,-16.75) 158(20.825,-16.25) 159(20.825,-15.75) 160(20.825,-15.25) 161(20.825,-14.75) 162(20.825,-14.25) 163(20.825,-13.75) 164(20.825,-13.25) 165(20.825,-12.75) 166(20.825,-12.25) 167(20.825,-11.75) 168(20.825,-11.25) 169(20.825,-10.75) 170(20.825,-10.25) 171(20.825,-9.75) 172(20.825,-9.25) 173(20.825,-8.75) 174(20.825,-8.25) 175(20.825,-7.75) 176(20.825,-7.25) 177(20.825,-6.75) 178(20.825,-6.25) 179(20.825,-5.75) 180(20.825,-5.25) 181(20.825,-4.75) 182(20.825,-4.25) 183(20.825,-3.75) 184(20.825,-3.25) 185(20.825,-2.75) 186(20.825,-2.25) 187(20.825,-1.75) 188(20.825,-1.25) 189(20.825,-0.75) 190(20.825,-0.25) 191(20.825,0.25) 192(20.825,0.75) 193(20.825,1.25) 194(20.825,1.75) 195(20.825,2.25) 196(20.825,2.75) 197(20.825,3.25) 198(20.825,3.75) 199(20.825,4.25) 200(20.825,4.75) 201(20.825,5.25) 202(20.825,5.75) 203(20.825,6.25) 204(20.825,6.75) 205(20.825,7.25) 206(20.825,7.75) 207(20.825,8.25) 208(20.825,8.75) 209(20.825,9.25) 210(20.825,9.75) 211(20.825,10.25) 212(20.825,10.75) 213(20.825,11.25) 214(20.825,11.75) 215(20.825,12.25) 216(20.825,12.75) 217(20.825,13.25) 218(20.825,13.75) 219(20.825,14.25) 220(20.825,14.75) 221(20.825,15.25) 222(20.825,15.75) 223(20.825,16.25) 224(20.825,16.75) 225(20.825,17.25) 226(20.825,17.75) 227(20.825,18.25) 228(20.825,18.75)
  oval 0.25x1.55 smd: 77(-18.75,-20.825) 78(-18.25,-20.825) 79(-17.75,-20.825) 80(-17.25,-20.825) 81(-16.75,-20.825) 82(-16.25,-20.825) 83(-15.75,-20.825) 84(-15.25,-20.825) 85(-14.75,-20.825) 86(-14.25,-20.825) 87(-13.75,-20.825) 88(-13.25,-20.825) 89(-12.75,-20.825) 90(-12.25,-20.825) 91(-11.75,-20.825) 92(-11.25,-20.825) 93(-10.75,-20.825) 94(-10.25,-20.825) 95(-9.75,-20.825) 96(-9.25,-20.825) 97(-8.75,-20.825) 98(-8.25,-20.825) 99(-7.75,-20.825) 100(-7.25,-20.825) 101(-6.75,-20.825) 102(-6.25,-20.825) 103(-5.75,-20.825) 104(-5.25,-20.825) 105(-4.75,-20.825) 106(-4.25,-20.825) 107(-3.75,-20.825) 108(-3.25,-20.825) 109(-2.75,-20.825) 110(-2.25,-20.825) 111(-1.75,-20.825) 112(-1.25,-20.825) 113(-0.75,-20.825) 114(-0.25,-20.825) 115(0.25,-20.825) 116(0.75,-20.825) 117(1.25,-20.825) 118(1.75,-20.825) 119(2.25,-20.825) 120(2.75,-20.825) 121(3.25,-20.825) 122(3.75,-20.825) 123(4.25,-20.825) 124(4.75,-20.825) 125(5.25,-20.825) 126(5.75,-20.825) 127(6.25,-20.825) 128(6.75,-20.825) 129(7.25,-20.825) 130(7.75,-20.825) 131(8.25,-20.825) 132(8.75,-20.825) 133(9.25,-20.825) 134(9.75,-20.825) 135(10.25,-20.825) 136(10.75,-20.825) 137(11.25,-20.825) 138(11.75,-20.825) 139(12.25,-20.825) 140(12.75,-20.825) 141(13.25,-20.825) 142(13.75,-20.825) 143(14.25,-20.825) 144(14.75,-20.825) 145(15.25,-20.825) 146(15.75,-20.825) 147(16.25,-20.825) 148(16.75,-20.825) 149(17.25,-20.825) 150(17.75,-20.825) 151(18.25,-20.825) 152(18.75,-20.825) 229(18.75,20.825) 230(18.25,20.825) 231(17.75,20.825) 232(17.25,20.825) 233(16.75,20.825) 234(16.25,20.825) 235(15.75,20.825) 236(15.25,20.825) 237(14.75,20.825) 238(14.25,20.825) 239(13.75,20.825) 240(13.25,20.825) 241(12.75,20.825) 242(12.25,20.825) 243(11.75,20.825) 244(11.25,20.825) 245(10.75,20.825) 246(10.25,20.825) 247(9.75,20.825) 248(9.25,20.825) 249(8.75,20.825) 250(8.25,20.825) 251(7.75,20.825) 252(7.25,20.825) 253(6.75,20.825) 254(6.25,20.825) 255(5.75,20.825) 256(5.25,20.825) 257(4.75,20.825) 258(4.25,20.825) 259(3.75,20.825) 260(3.25,20.825) 261(2.75,20.825) 262(2.25,20.825) 263(1.75,20.825) 264(1.25,20.825) 265(0.75,20.825) 266(0.25,20.825) 267(-0.25,20.825) 268(-0.75,20.825) 269(-1.25,20.825) 270(-1.75,20.825) 271(-2.25,20.825) 272(-2.75,20.825) 273(-3.25,20.825) 274(-3.75,20.825) 275(-4.25,20.825) 276(-4.75,20.825) 277(-5.25,20.825) 278(-5.75,20.825) 279(-6.25,20.825) 280(-6.75,20.825) 281(-7.25,20.825) 282(-7.75,20.825) 283(-8.25,20.825) 284(-8.75,20.825) 285(-9.25,20.825) 286(-9.75,20.825) 287(-10.25,20.825) 288(-10.75,20.825) 289(-11.25,20.825) 290(-11.75,20.825) 291(-12.25,20.825) 292(-12.75,20.825) 293(-13.25,20.825) 294(-13.75,20.825) 295(-14.25,20.825) 296(-14.75,20.825) 297(-15.25,20.825) 298(-15.75,20.825) 299(-16.25,20.825) 300(-16.75,20.825) 301(-17.25,20.825) 302(-17.75,20.825) 303(-18.25,20.825) 304(-18.75,20.825)
Top Overlay:
  circle w0.25: c-20.825,19.425 r0.125
  circle w0.6: c-18.65,18.65 r0.3
  lines w0.2: -19.65,-19.65 -19.65,19.65 19.65,19.65 19.65,-19.65 -19.65,-19.65
Mechanical 13:
  circle w0.1: c-19.1,19.1 r0.5
  lines w0.1: -20,-20 -20,20 20,20 20,-20 -20,-20
Mechanical 15:
  lines w0.1: -0.5,0 0.5,0 ; 0,-0.5 0,0.5 ; -21.7,-21.7 -21.7,21.7 21.7,21.7 21.7,-21.7 -21.7,-21.7
3D body: height 4.5, standoff 0, extent -20,-20 20,20

## HQ304_M [mm] "304-Pin Heat Sink Quad Flat Pack (HQ304), IPC Low Density"
height 4.5
pads (304):
  oval 2.1x0.3 smd: 1(-20.9,18.75) 2(-20.9,18.25) 3(-20.9,17.75) 4(-20.9,17.25) 5(-20.9,16.75) 6(-20.9,16.25) 7(-20.9,15.75) 8(-20.9,15.25) 9(-20.9,14.75) 10(-20.9,14.25) 11(-20.9,13.75) 12(-20.9,13.25) 13(-20.9,12.75) 14(-20.9,12.25) 15(-20.9,11.75) 16(-20.9,11.25) 17(-20.9,10.75) 18(-20.9,10.25) 19(-20.9,9.75) 20(-20.9,9.25) 21(-20.9,8.75) 22(-20.9,8.25) 23(-20.9,7.75) 24(-20.9,7.25) 25(-20.9,6.75) 26(-20.9,6.25) 27(-20.9,5.75) 28(-20.9,5.25) 29(-20.9,4.75) 30(-20.9,4.25) 31(-20.9,3.75) 32(-20.9,3.25) 33(-20.9,2.75) 34(-20.9,2.25) 35(-20.9,1.75) 36(-20.9,1.25) 37(-20.9,0.75) 38(-20.9,0.25) 39(-20.9,-0.25) 40(-20.9,-0.75) 41(-20.9,-1.25) 42(-20.9,-1.75) 43(-20.9,-2.25) 44(-20.9,-2.75) 45(-20.9,-3.25) 46(-20.9,-3.75) 47(-20.9,-4.25) 48(-20.9,-4.75) 49(-20.9,-5.25) 50(-20.9,-5.75) 51(-20.9,-6.25) 52(-20.9,-6.75) 53(-20.9,-7.25) 54(-20.9,-7.75) 55(-20.9,-8.25) 56(-20.9,-8.75) 57(-20.9,-9.25) 58(-20.9,-9.75) 59(-20.9,-10.25) 60(-20.9,-10.75) 61(-20.9,-11.25) 62(-20.9,-11.75) 63(-20.9,-12.25) 64(-20.9,-12.75) 65(-20.9,-13.25) 66(-20.9,-13.75) 67(-20.9,-14.25) 68(-20.9,-14.75) 69(-20.9,-15.25) 70(-20.9,-15.75) 71(-20.9,-16.25) 72(-20.9,-16.75) 73(-20.9,-17.25) 74(-20.9,-17.75) 75(-20.9,-18.25) 76(-20.9,-18.75) 153(20.9,-18.75) 154(20.9,-18.25) 155(20.9,-17.75) 156(20.9,-17.25) 157(20.9,-16.75) 158(20.9,-16.25) 159(20.9,-15.75) 160(20.9,-15.25) 161(20.9,-14.75) 162(20.9,-14.25) 163(20.9,-13.75) 164(20.9,-13.25) 165(20.9,-12.75) 166(20.9,-12.25) 167(20.9,-11.75) 168(20.9,-11.25) 169(20.9,-10.75) 170(20.9,-10.25) 171(20.9,-9.75) 172(20.9,-9.25) 173(20.9,-8.75) 174(20.9,-8.25) 175(20.9,-7.75) 176(20.9,-7.25) 177(20.9,-6.75) 178(20.9,-6.25) 179(20.9,-5.75) 180(20.9,-5.25) 181(20.9,-4.75) 182(20.9,-4.25) 183(20.9,-3.75) 184(20.9,-3.25) 185(20.9,-2.75) 186(20.9,-2.25) 187(20.9,-1.75) 188(20.9,-1.25) 189(20.9,-0.75) 190(20.9,-0.25) 191(20.9,0.25) 192(20.9,0.75) 193(20.9,1.25) 194(20.9,1.75) 195(20.9,2.25) 196(20.9,2.75) 197(20.9,3.25) 198(20.9,3.75) 199(20.9,4.25) 200(20.9,4.75) 201(20.9,5.25) 202(20.9,5.75) 203(20.9,6.25) 204(20.9,6.75) 205(20.9,7.25) 206(20.9,7.75) 207(20.9,8.25) 208(20.9,8.75) 209(20.9,9.25) 210(20.9,9.75) 211(20.9,10.25) 212(20.9,10.75) 213(20.9,11.25) 214(20.9,11.75) 215(20.9,12.25) 216(20.9,12.75) 217(20.9,13.25) 218(20.9,13.75) 219(20.9,14.25) 220(20.9,14.75) 221(20.9,15.25) 222(20.9,15.75) 223(20.9,16.25) 224(20.9,16.75) 225(20.9,17.25) 226(20.9,17.75) 227(20.9,18.25) 228(20.9,18.75)
  oval 0.3x2.1 smd: 77(-18.75,-20.9) 78(-18.25,-20.9) 79(-17.75,-20.9) 80(-17.25,-20.9) 81(-16.75,-20.9) 82(-16.25,-20.9) 83(-15.75,-20.9) 84(-15.25,-20.9) 85(-14.75,-20.9) 86(-14.25,-20.9) 87(-13.75,-20.9) 88(-13.25,-20.9) 89(-12.75,-20.9) 90(-12.25,-20.9) 91(-11.75,-20.9) 92(-11.25,-20.9) 93(-10.75,-20.9) 94(-10.25,-20.9) 95(-9.75,-20.9) 96(-9.25,-20.9) 97(-8.75,-20.9) 98(-8.25,-20.9) 99(-7.75,-20.9) 100(-7.25,-20.9) 101(-6.75,-20.9) 102(-6.25,-20.9) 103(-5.75,-20.9) 104(-5.25,-20.9) 105(-4.75,-20.9) 106(-4.25,-20.9) 107(-3.75,-20.9) 108(-3.25,-20.9) 109(-2.75,-20.9) 110(-2.25,-20.9) 111(-1.75,-20.9) 112(-1.25,-20.9) 113(-0.75,-20.9) 114(-0.25,-20.9) 115(0.25,-20.9) 116(0.75,-20.9) 117(1.25,-20.9) 118(1.75,-20.9) 119(2.25,-20.9) 120(2.75,-20.9) 121(3.25,-20.9) 122(3.75,-20.9) 123(4.25,-20.9) 124(4.75,-20.9) 125(5.25,-20.9) 126(5.75,-20.9) 127(6.25,-20.9) 128(6.75,-20.9) 129(7.25,-20.9) 130(7.75,-20.9) 131(8.25,-20.9) 132(8.75,-20.9) 133(9.25,-20.9) 134(9.75,-20.9) 135(10.25,-20.9) 136(10.75,-20.9) 137(11.25,-20.9) 138(11.75,-20.9) 139(12.25,-20.9) 140(12.75,-20.9) 141(13.25,-20.9) 142(13.75,-20.9) 143(14.25,-20.9) 144(14.75,-20.9) 145(15.25,-20.9) 146(15.75,-20.9) 147(16.25,-20.9) 148(16.75,-20.9) 149(17.25,-20.9) 150(17.75,-20.9) 151(18.25,-20.9) 152(18.75,-20.9) 229(18.75,20.9) 230(18.25,20.9) 231(17.75,20.9) 232(17.25,20.9) 233(16.75,20.9) 234(16.25,20.9) 235(15.75,20.9) 236(15.25,20.9) 237(14.75,20.9) 238(14.25,20.9) 239(13.75,20.9) 240(13.25,20.9) 241(12.75,20.9) 242(12.25,20.9) 243(11.75,20.9) 244(11.25,20.9) 245(10.75,20.9) 246(10.25,20.9) 247(9.75,20.9) 248(9.25,20.9) 249(8.75,20.9) 250(8.25,20.9) 251(7.75,20.9) 252(7.25,20.9) 253(6.75,20.9) 254(6.25,20.9) 255(5.75,20.9) 256(5.25,20.9) 257(4.75,20.9) 258(4.25,20.9) 259(3.75,20.9) 260(3.25,20.9) 261(2.75,20.9) 262(2.25,20.9) 263(1.75,20.9) 264(1.25,20.9) 265(0.75,20.9) 266(0.25,20.9) 267(-0.25,20.9) 268(-0.75,20.9) 269(-1.25,20.9) 270(-1.75,20.9) 271(-2.25,20.9) 272(-2.75,20.9) 273(-3.25,20.9) 274(-3.75,20.9) 275(-4.25,20.9) 276(-4.75,20.9) 277(-5.25,20.9) 278(-5.75,20.9) 279(-6.25,20.9) 280(-6.75,20.9) 281(-7.25,20.9) 282(-7.75,20.9) 283(-8.25,20.9) 284(-8.75,20.9) 285(-9.25,20.9) 286(-9.75,20.9) 287(-10.25,20.9) 288(-10.75,20.9) 289(-11.25,20.9) 290(-11.75,20.9) 291(-12.25,20.9) 292(-12.75,20.9) 293(-13.25,20.9) 294(-13.75,20.9) 295(-14.25,20.9) 296(-14.75,20.9) 297(-15.25,20.9) 298(-15.75,20.9) 299(-16.25,20.9) 300(-16.75,20.9) 301(-17.25,20.9) 302(-17.75,20.9) 303(-18.25,20.9) 304(-18.75,20.9)
Top Overlay:
  circle w0.6: c-18.45,18.45 r0.3
  circle w0.25: c-20.9,19.45 r0.125
  lines w0.2: -19.45,-19.45 19.45,-19.45 19.45,19.45 -19.45,19.45 -19.45,-19.45
Mechanical 13:
  circle w0.1: c-19.1,19.1 r0.5
  lines w0.1: -20,-20 20,-20 20,20 -20,20 -20,-20
Mechanical 15:
  lines w0.1: -0.5,0 0.5,0 ; 0,-0.5 0,0.5 ; -22.45,-22.45 22.45,-22.45 22.45,22.45 -22.45,22.45 -22.45,-22.45
3D body: height 4.5, standoff 0, extent -20,-20 20,20

## HQ304_N [mm] "304-Pin Heat Sink Quad Flat Pack (HQ304), IPC Medium Density"
height 4.5
pads (304):
  oval 1.8x0.3 smd: 1(-20.85,18.75) 2(-20.85,18.25) 3(-20.85,17.75) 4(-20.85,17.25) 5(-20.85,16.75) 6(-20.85,16.25) 7(-20.85,15.75) 8(-20.85,15.25) 9(-20.85,14.75) 10(-20.85,14.25) 11(-20.85,13.75) 12(-20.85,13.25) 13(-20.85,12.75) 14(-20.85,12.25) 15(-20.85,11.75) 16(-20.85,11.25) 17(-20.85,10.75) 18(-20.85,10.25) 19(-20.85,9.75) 20(-20.85,9.25) 21(-20.85,8.75) 22(-20.85,8.25) 23(-20.85,7.75) 24(-20.85,7.25) 25(-20.85,6.75) 26(-20.85,6.25) 27(-20.85,5.75) 28(-20.85,5.25) 29(-20.85,4.75) 30(-20.85,4.25) 31(-20.85,3.75) 32(-20.85,3.25) 33(-20.85,2.75) 34(-20.85,2.25) 35(-20.85,1.75) 36(-20.85,1.25) 37(-20.85,0.75) 38(-20.85,0.25) 39(-20.85,-0.25) 40(-20.85,-0.75) 41(-20.85,-1.25) 42(-20.85,-1.75) 43(-20.85,-2.25) 44(-20.85,-2.75) 45(-20.85,-3.25) 46(-20.85,-3.75) 47(-20.85,-4.25) 48(-20.85,-4.75) 49(-20.85,-5.25) 50(-20.85,-5.75) 51(-20.85,-6.25) 52(-20.85,-6.75) 53(-20.85,-7.25) 54(-20.85,-7.75) 55(-20.85,-8.25) 56(-20.85,-8.75) 57(-20.85,-9.25) 58(-20.85,-9.75) 59(-20.85,-10.25) 60(-20.85,-10.75) 61(-20.85,-11.25) 62(-20.85,-11.75) 63(-20.85,-12.25) 64(-20.85,-12.75) 65(-20.85,-13.25) 66(-20.85,-13.75) 67(-20.85,-14.25) 68(-20.85,-14.75) 69(-20.85,-15.25) 70(-20.85,-15.75) 71(-20.85,-16.25) 72(-20.85,-16.75) 73(-20.85,-17.25) 74(-20.85,-17.75) 75(-20.85,-18.25) 76(-20.85,-18.75) 153(20.85,-18.75) 154(20.85,-18.25) 155(20.85,-17.75) 156(20.85,-17.25) 157(20.85,-16.75) 158(20.85,-16.25) 159(20.85,-15.75) 160(20.85,-15.25) 161(20.85,-14.75) 162(20.85,-14.25) 163(20.85,-13.75) 164(20.85,-13.25) 165(20.85,-12.75) 166(20.85,-12.25) 167(20.85,-11.75) 168(20.85,-11.25) 169(20.85,-10.75) 170(20.85,-10.25) 171(20.85,-9.75) 172(20.85,-9.25) 173(20.85,-8.75) 174(20.85,-8.25) 175(20.85,-7.75) 176(20.85,-7.25) 177(20.85,-6.75) 178(20.85,-6.25) 179(20.85,-5.75) 180(20.85,-5.25) 181(20.85,-4.75) 182(20.85,-4.25) 183(20.85,-3.75) 184(20.85,-3.25) 185(20.85,-2.75) 186(20.85,-2.25) 187(20.85,-1.75) 188(20.85,-1.25) 189(20.85,-0.75) 190(20.85,-0.25) 191(20.85,0.25) 192(20.85,0.75) 193(20.85,1.25) 194(20.85,1.75) 195(20.85,2.25) 196(20.85,2.75) 197(20.85,3.25) 198(20.85,3.75) 199(20.85,4.25) 200(20.85,4.75) 201(20.85,5.25) 202(20.85,5.75) 203(20.85,6.25) 204(20.85,6.75) 205(20.85,7.25) 206(20.85,7.75) 207(20.85,8.25) 208(20.85,8.75) 209(20.85,9.25) 210(20.85,9.75) 211(20.85,10.25) 212(20.85,10.75) 213(20.85,11.25) 214(20.85,11.75) 215(20.85,12.25) 216(20.85,12.75) 217(20.85,13.25) 218(20.85,13.75) 219(20.85,14.25) 220(20.85,14.75) 221(20.85,15.25) 222(20.85,15.75) 223(20.85,16.25) 224(20.85,16.75) 225(20.85,17.25) 226(20.85,17.75) 227(20.85,18.25) 228(20.85,18.75)
  oval 0.3x1.8 smd: 77(-18.75,-20.85) 78(-18.25,-20.85) 79(-17.75,-20.85) 80(-17.25,-20.85) 81(-16.75,-20.85) 82(-16.25,-20.85) 83(-15.75,-20.85) 84(-15.25,-20.85) 85(-14.75,-20.85) 86(-14.25,-20.85) 87(-13.75,-20.85) 88(-13.25,-20.85) 89(-12.75,-20.85) 90(-12.25,-20.85) 91(-11.75,-20.85) 92(-11.25,-20.85) 93(-10.75,-20.85) 94(-10.25,-20.85) 95(-9.75,-20.85) 96(-9.25,-20.85) 97(-8.75,-20.85) 98(-8.25,-20.85) 99(-7.75,-20.85) 100(-7.25,-20.85) 101(-6.75,-20.85) 102(-6.25,-20.85) 103(-5.75,-20.85) 104(-5.25,-20.85) 105(-4.75,-20.85) 106(-4.25,-20.85) 107(-3.75,-20.85) 108(-3.25,-20.85) 109(-2.75,-20.85) 110(-2.25,-20.85) 111(-1.75,-20.85) 112(-1.25,-20.85) 113(-0.75,-20.85) 114(-0.25,-20.85) 115(0.25,-20.85) 116(0.75,-20.85) 117(1.25,-20.85) 118(1.75,-20.85) 119(2.25,-20.85) 120(2.75,-20.85) 121(3.25,-20.85) 122(3.75,-20.85) 123(4.25,-20.85) 124(4.75,-20.85) 125(5.25,-20.85) 126(5.75,-20.85) 127(6.25,-20.85) 128(6.75,-20.85) 129(7.25,-20.85) 130(7.75,-20.85) 131(8.25,-20.85) 132(8.75,-20.85) 133(9.25,-20.85) 134(9.75,-20.85) 135(10.25,-20.85) 136(10.75,-20.85) 137(11.25,-20.85) 138(11.75,-20.85) 139(12.25,-20.85) 140(12.75,-20.85) 141(13.25,-20.85) 142(13.75,-20.85) 143(14.25,-20.85) 144(14.75,-20.85) 145(15.25,-20.85) 146(15.75,-20.85) 147(16.25,-20.85) 148(16.75,-20.85) 149(17.25,-20.85) 150(17.75,-20.85) 151(18.25,-20.85) 152(18.75,-20.85) 229(18.75,20.85) 230(18.25,20.85) 231(17.75,20.85) 232(17.25,20.85) 233(16.75,20.85) 234(16.25,20.85) 235(15.75,20.85) 236(15.25,20.85) 237(14.75,20.85) 238(14.25,20.85) 239(13.75,20.85) 240(13.25,20.85) 241(12.75,20.85) 242(12.25,20.85) 243(11.75,20.85) 244(11.25,20.85) 245(10.75,20.85) 246(10.25,20.85) 247(9.75,20.85) 248(9.25,20.85) 249(8.75,20.85) 250(8.25,20.85) 251(7.75,20.85) 252(7.25,20.85) 253(6.75,20.85) 254(6.25,20.85) 255(5.75,20.85) 256(5.25,20.85) 257(4.75,20.85) 258(4.25,20.85) 259(3.75,20.85) 260(3.25,20.85) 261(2.75,20.85) 262(2.25,20.85) 263(1.75,20.85) 264(1.25,20.85) 265(0.75,20.85) 266(0.25,20.85) 267(-0.25,20.85) 268(-0.75,20.85) 269(-1.25,20.85) 270(-1.75,20.85) 271(-2.25,20.85) 272(-2.75,20.85) 273(-3.25,20.85) 274(-3.75,20.85) 275(-4.25,20.85) 276(-4.75,20.85) 277(-5.25,20.85) 278(-5.75,20.85) 279(-6.25,20.85) 280(-6.75,20.85) 281(-7.25,20.85) 282(-7.75,20.85) 283(-8.25,20.85) 284(-8.75,20.85) 285(-9.25,20.85) 286(-9.75,20.85) 287(-10.25,20.85) 288(-10.75,20.85) 289(-11.25,20.85) 290(-11.75,20.85) 291(-12.25,20.85) 292(-12.75,20.85) 293(-13.25,20.85) 294(-13.75,20.85) 295(-14.25,20.85) 296(-14.75,20.85) 297(-15.25,20.85) 298(-15.75,20.85) 299(-16.25,20.85) 300(-16.75,20.85) 301(-17.25,20.85) 302(-17.75,20.85) 303(-18.25,20.85) 304(-18.75,20.85)
Top Overlay:
  circle w0.6: c-18.55,18.55 r0.3
  circle w0.25: c-20.85,19.45 r0.125
  lines w0.2: -19.55,-19.55 19.55,-19.55 19.55,19.55 -19.55,19.55 -19.55,-19.55
Mechanical 13:
  circle w0.1: c-19.1,19.1 r0.5
  lines w0.1: -20,-20 20,-20 20,20 -20,20 -20,-20
Mechanical 15:
  lines w0.1: -0.5,0 0.5,0 ; 0,-0.5 0,0.5 ; -22,-22 22,-22 22,22 -22,22 -22,-22
3D body: height 4.5, standoff 0, extent -20,-20 20,20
